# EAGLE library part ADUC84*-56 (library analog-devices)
MicroConverter® Multichannel 24-/16-Bit ADCs with Embedded 62 kB Flash and Single-Cycle MCU Source: http://www.analog.com/static/imported-files/data_sheets/ADUC845_847_848.pdf
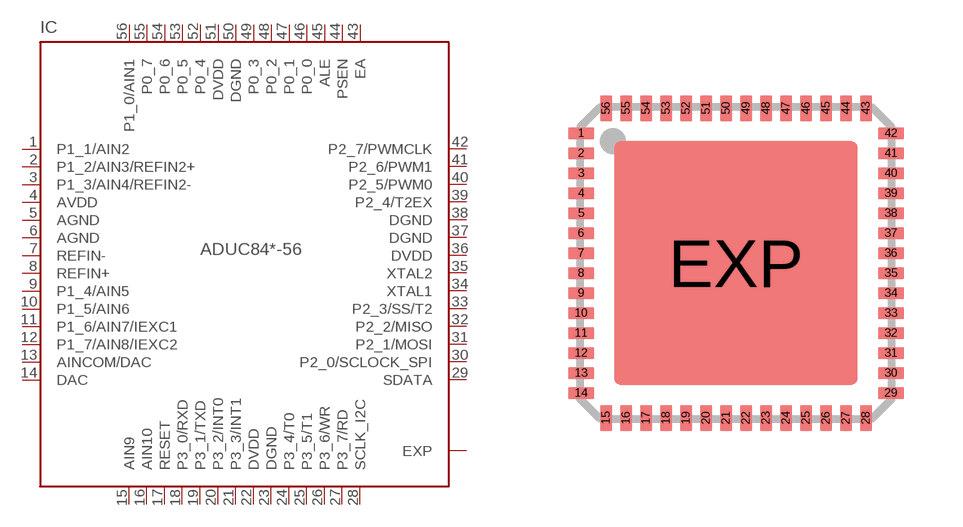
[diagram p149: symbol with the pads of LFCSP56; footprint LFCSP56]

Designator prefix IC

## ADUC845-56 (OC_FARNELL: unknown; OC_NEWARK: unknown), ADUC847-56 (OC_FARNELL: unknown; OC_NEWARK: unknown), ADUC848-56 (OC_FARNELL: unknown; OC_NEWARK: unknown)  [LFCSP56]
1  P1_1/AIN2  in
2  P1_2/AIN3/REFIN2+  in
3  P1_3/AIN4/REFIN2-  in
4  AVDD  pwr
5  AGND  pwr
6  AGND  pwr
7  REFIN-  in
8  REFIN+  in
9  P1_4/AIN5  in
10  P1_5/AIN6  in
11  P1_6/AIN7/IEXC1
12  P1_7/AIN8/IEXC2
13  AINCOM/DAC
14  DAC  out
15  AIN9  in
16  AIN10  in
17  RESET  in
18  P3_0/RXD
19  P3_1/TXD
20  P3_2/INT0
21  P3_3/INT1
22  DVDD  pwr
23  DGND  pwr
24  P3_4/T0
25  P3_5/T1
26  P3_6/WR
27  P3_7/RD
28  SCLK_I2C
29  SDATA
30  P2_0/SCLOCK_SPI
31  P2_1/MOSI
32  P2_2/MISO
33  P2_3/SS/T2
34  XTAL1  in
35  XTAL2  out
36  DVDD  pwr
37  DGND  pwr
38  DGND  pwr
39  P2_4/T2EX
40  P2_5/PWM0
41  P2_6/PWM1
42  P2_7/PWMCLK
43  EA  in
44  PSEN  out
45  ALE  out
46  P0_0
47  P0_1
48  P0_2
49  P0_3
50  DGND  pwr
51  DVDD  pwr
52  P0_4
53  P0_5
54  P0_6
55  P0_7
56  P1_0/AIN1  in
EXP  EXP  pas

## Footprint LFCSP56 (pad centres in mm)
56-Lead Frame Chip Scale Package LFCSP 8 mm × 8 mm Body, Very Thin Quad (CP-56) COMPLIANT TO JEDEC STANDARDS MO-220-VLLD-2 Source: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
smd 0.65 x 0.3: 1 -3.875,3.25; 2 -3.875,2.75; 3 -3.875,2.25; 4 -3.875,1.75; 5 -3.875,1.25; 6 -3.875,0.75; 7 -3.875,0.25; 8 -3.875,-0.25; 9 -3.875,-0.75; 10 -3.875,-1.25; 11 -3.875,-1.75; 12 -3.875,-2.25; 13 -3.875,-2.75; 14 -3.875,-3.25; 29 3.875,-3.25; 30 3.875,-2.75; 31 3.875,-2.25; 32 3.875,-1.75; 33 3.875,-1.25; 34 3.875,-0.75; 35 3.875,-0.25; 36 3.875,0.25; 37 3.875,0.75; 38 3.875,1.25; 39 3.875,1.75; 40 3.875,2.25; 41 3.875,2.75; 42 3.875,3.25
smd 0.3 x 0.65: 15 -3.25,-3.875; 16 -2.75,-3.875; 17 -2.25,-3.875; 18 -1.75,-3.875; 19 -1.25,-3.875; 20 -0.75,-3.875; 21 -0.25,-3.875; 22 0.25,-3.875; 23 0.75,-3.875; 24 1.25,-3.875; 25 1.75,-3.875; 26 2.25,-3.875; 27 2.75,-3.875; 28 3.25,-3.875; 43 3.25,3.875; 44 2.75,3.875; 45 2.25,3.875; 46 1.75,3.875; 47 1.25,3.875; 48 0.75,3.875; 49 0.25,3.875; 50 -0.25,3.875; 51 -0.75,3.875; 52 -1.25,3.875; 53 -1.75,3.875; 54 -2.25,3.875; 55 -2.75,3.875; 56 -3.25,3.875
smd 6.1 x 6.1: EXP 0,0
